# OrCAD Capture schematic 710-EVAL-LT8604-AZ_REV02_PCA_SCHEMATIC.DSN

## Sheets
1 PAGE1
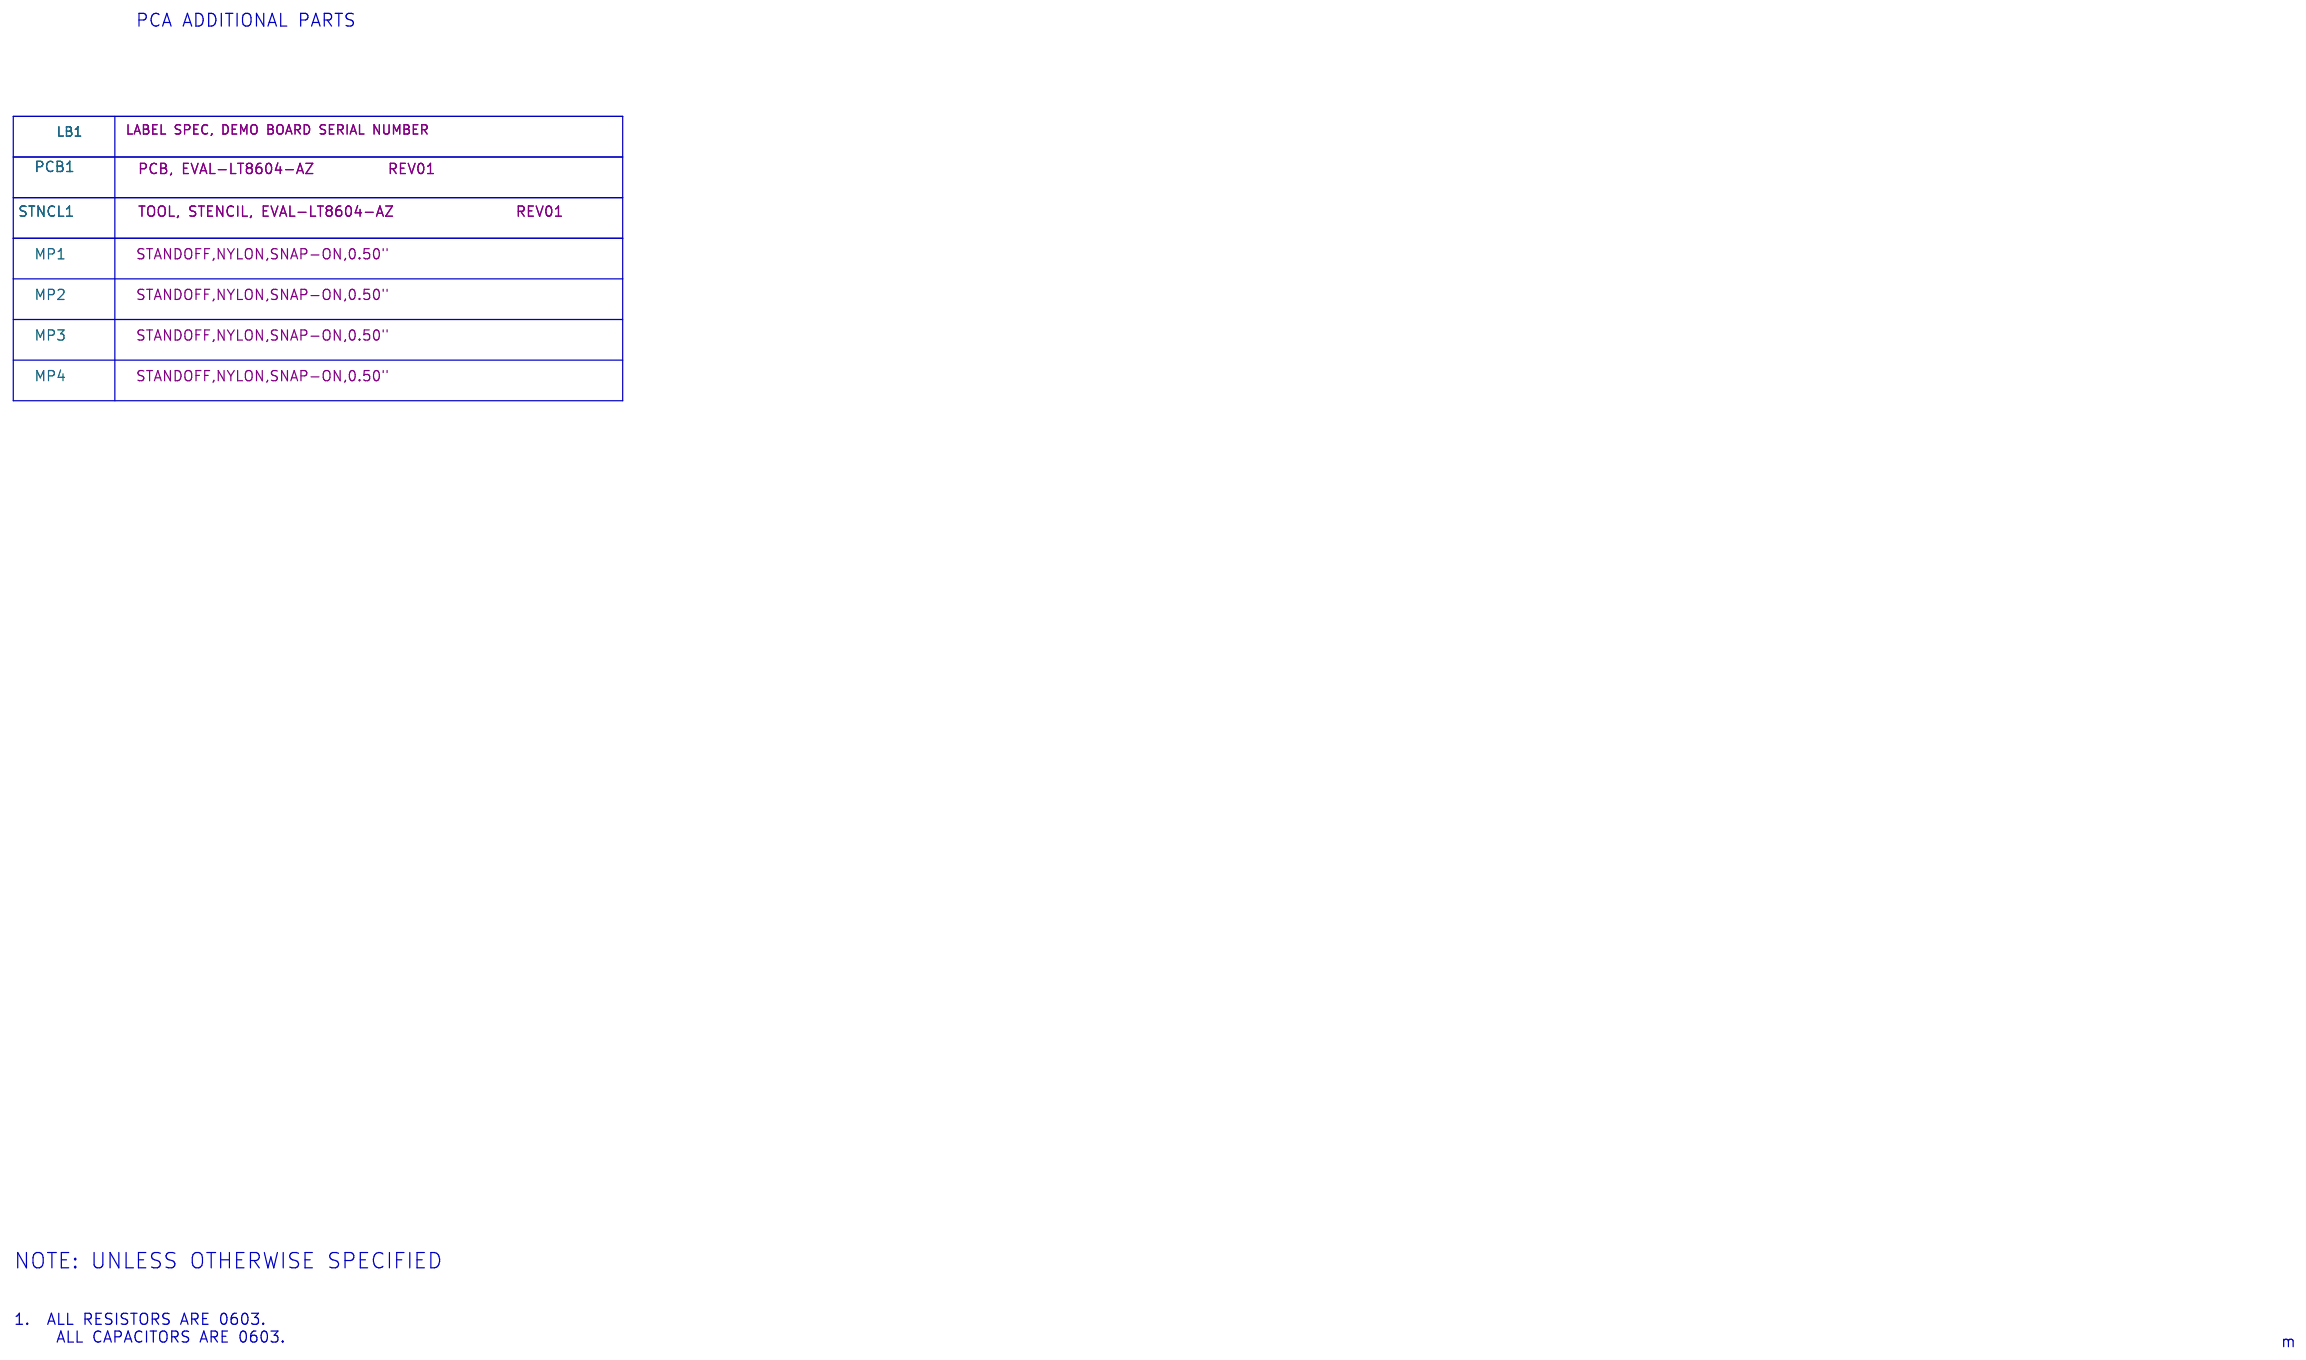
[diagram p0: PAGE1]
2 LT8604: size Custom; company: ANALOG DEVICES; note: DEMO BOARD BILL OF MATERIALS; note: HIGH EFFICIENCY 42V/120mA SYNCHRONOUS BUCK
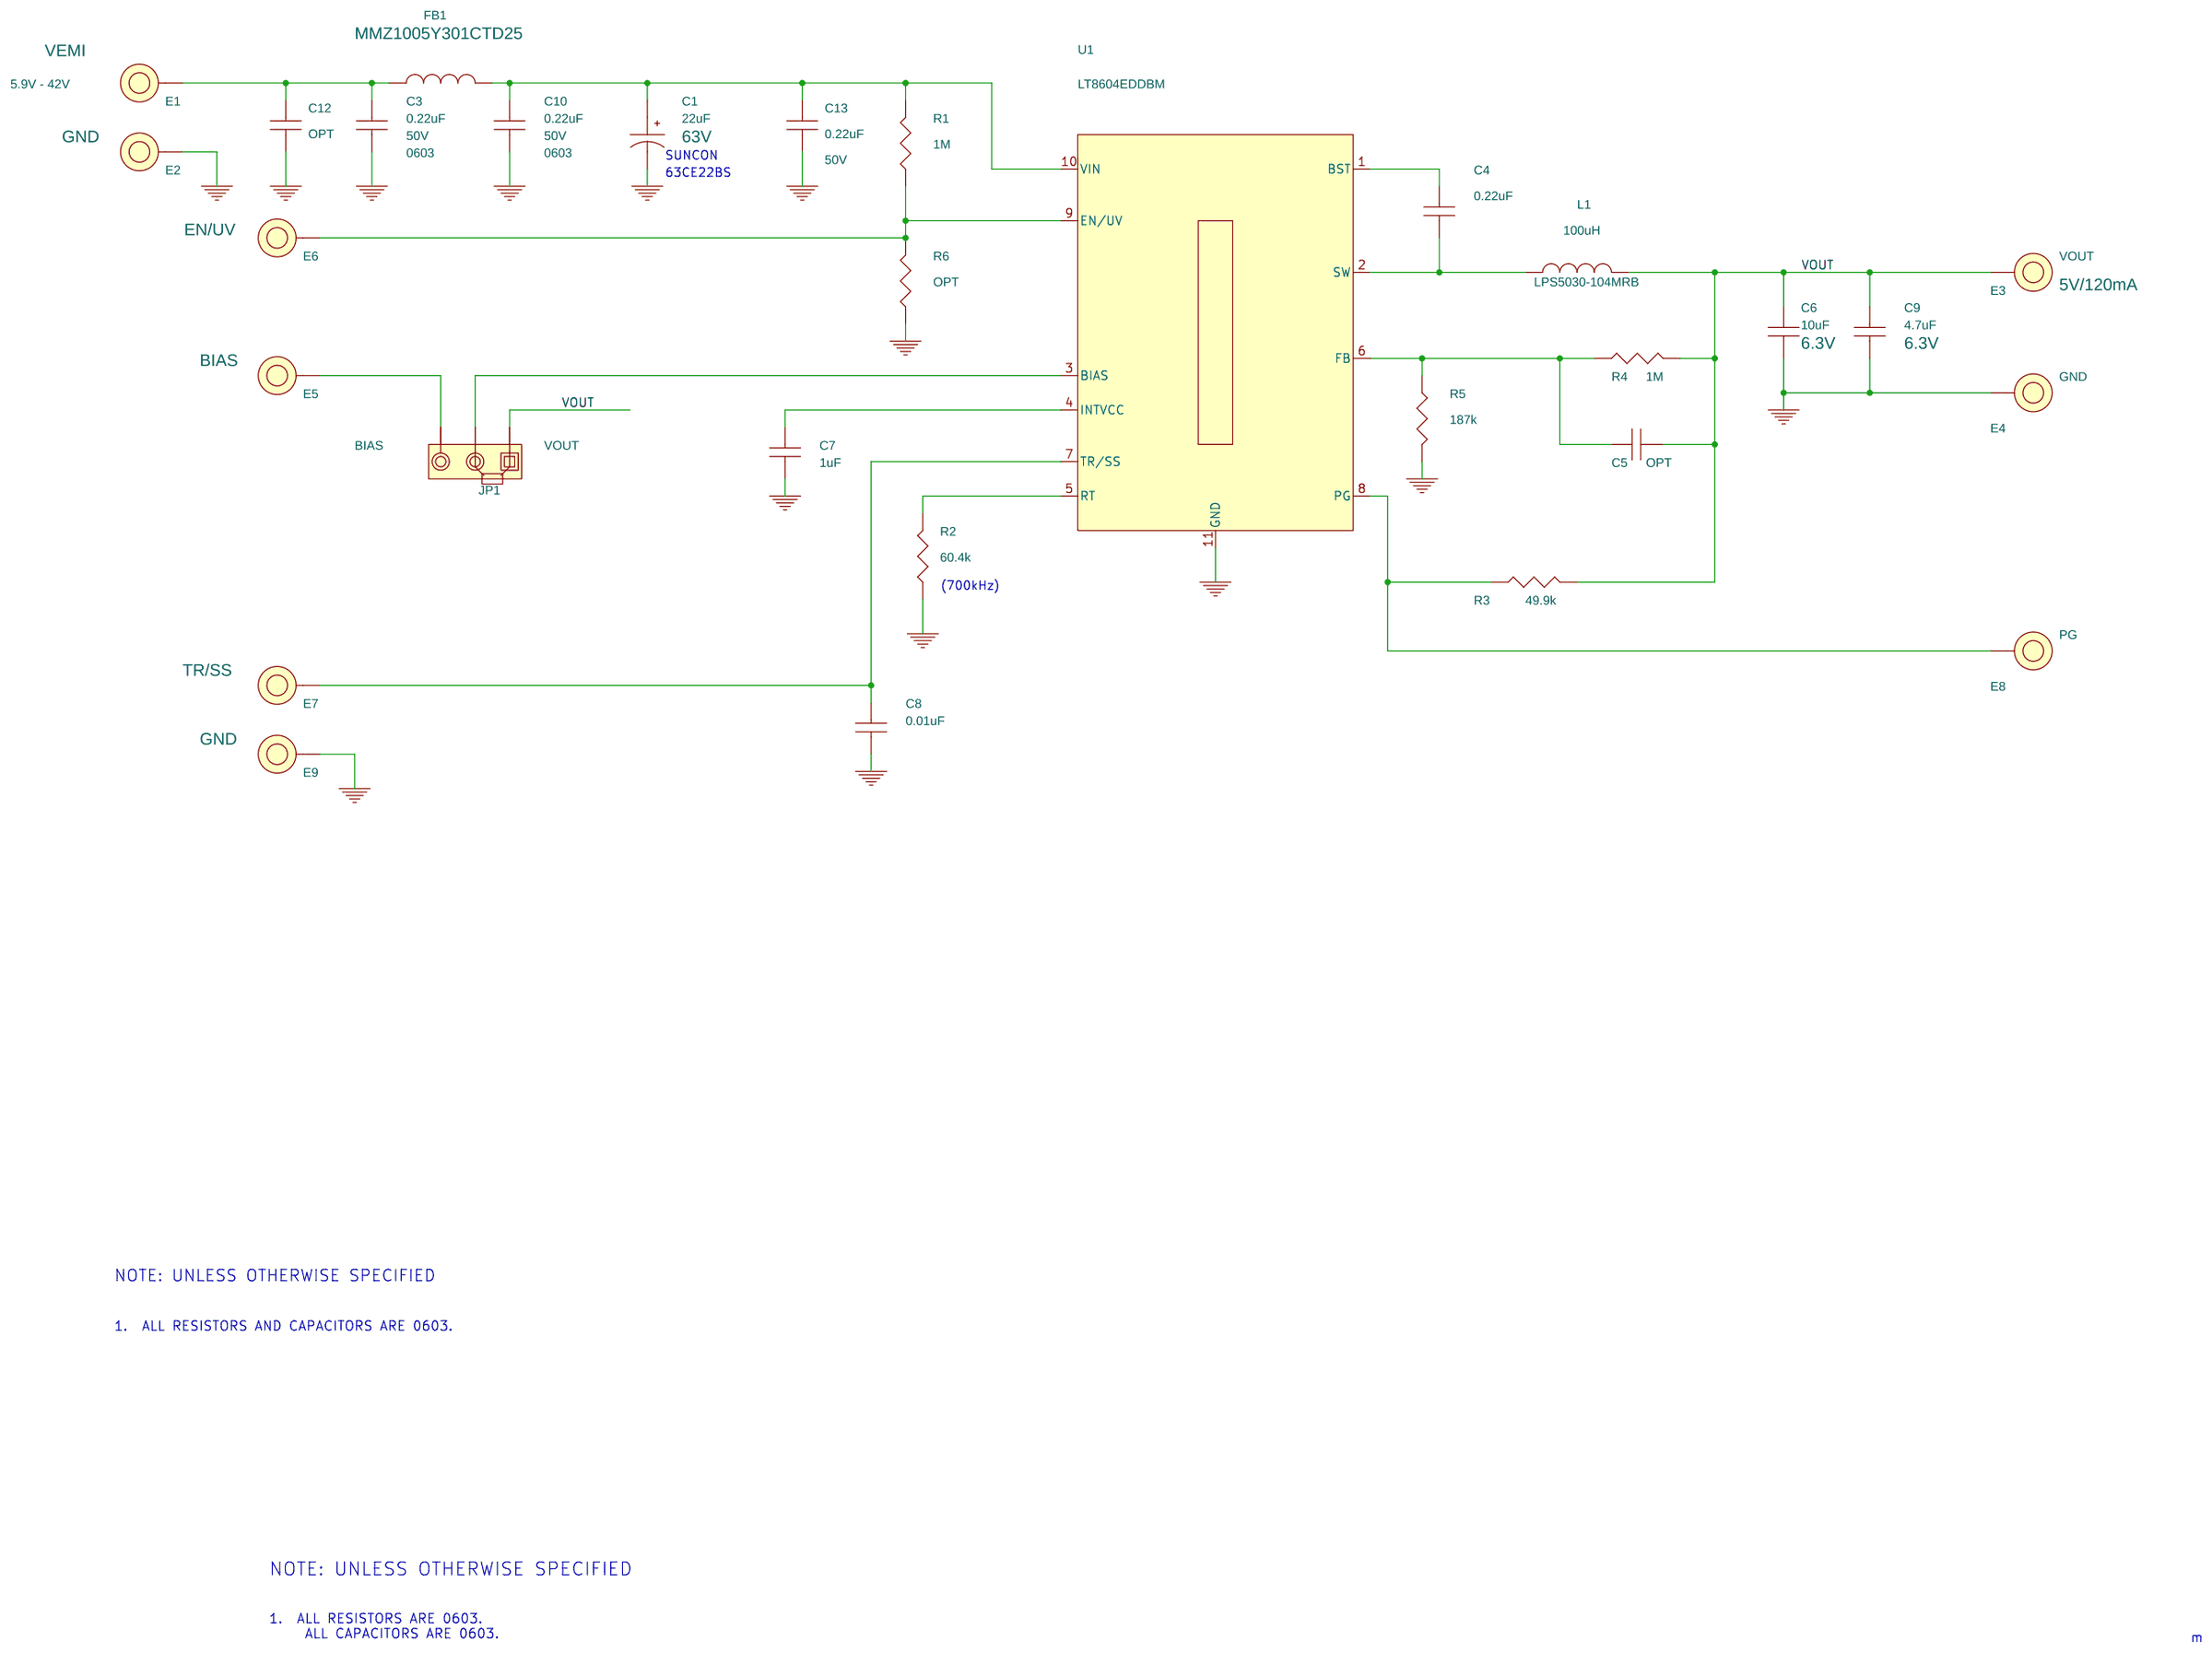
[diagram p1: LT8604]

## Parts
sheet LT8604
C1  22uF  [SUNCON_CE-BS_6.3X7.7]
C3  0.22uF  [CC0603N]
C4  0.22uF  [CC0603N]
C5  OPT  [CC0603N]
C6  10uF  [CC0603N]
C7  1uF  [CC0603N]
C8  0.01uF  [CC0603N]
C9  4.7uF  [CC0603N]
C10  0.22uF  [CC0603N]
C12  OPT  [CC0603N]
C13  0.22uF  [CC0603N]
E1  TEST POINT  [MILLMAX2501]
E2  TEST POINT  [MILLMAX2501]
E3  TEST POINT  [MILLMAX2501]
E4  TEST POINT  [MILLMAX2501]
E5  TEST POINT  [MILLMAX2501]
E6  TEST POINT  [MILLMAX2501]
E7  TEST POINT  [MILLMAX2501]
E8  TEST POINT  [MILLMAX2501]
E9  TEST POINT  [MILLMAX2501]
FB1  300 OHMS@100MHz  [IND0402N]
JP1  HDR  [HD1X3-079]
L1  100uH  [COILCRAFT-LPS5030]
R1  1M  [CR0603N]
R2  60.4k  [CR0603N]
R3  49.9k  [CR0603N]
R4  1M  [CR0603N]
R5  187k  [CR0603N]
R6  OPT  [CR0603N]
U1  LT8604EDDBM  [LTC-DFN-10-1722]
XJP1  SHUNT
sheet PAGE1
LB1  LABEL  [895-0154_REV01]
MP1  STANDOFF  [KEYSTONE_8829-8834]
MP2  STANDOFF  [KEYSTONE_8829-8834]
MP3  STANDOFF  [KEYSTONE_8829-8834]
MP4  STANDOFF  [KEYSTONE_8829-8834]
PCB1  PCB, EVAL-LT8604-AZ
STNCL1  TOOL, STENCIL, EVAL-LT8604-AZ

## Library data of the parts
C1 = CAP_P: CAP.,22uF,ALUM ELECT,63V,20%,6.3x7.7mm,CE-BS Series; CLASS: DISCRETE; Dielectric Type: ALUM ELECT; Inventory Qty: 35661; Manufacturer: SUN ELECTRONIC INDUSTRIES CORP; Manufacturer PN: 63CE22BS; PART_NUMBER: 150-3334; Package Size: 6.3x7.7mm; Rated Voltage: 63V; Tolerance: 20%
C3 C10 C13 = CAP: CAP.,0.22uF,X7R,50V,10%,0603,AEC-Q200; CLASS: DISCRETE; Dielectric Type: X7R; FPLIST: CC0603N,CC0603L,CC0603M; Inventory Qty: 270; Manufacturer: MURATA; Manufacturer PN: GCM188R71H224KA64D; PART_NUMBER: 150-1665; Package Size: 0603; Package Type: Surface Mount, MLCC; Rated Voltage: 50V; Temperature Coefficient: X7R; Tolerance: 10%
C4 = CAP: CAP.,0.22uF,X7R,16V,10%,0603; CLASS: DISCRETE; Dielectric Type: X7R; FPLIST: CC0603N,CC0603L,CC0603M; Inventory Qty: 17079; Manufacturer: AVX; Manufacturer PN: 0603YC224KAT2A; PART_NUMBER: 150-0181; Package Size: 0603; Rated Voltage: 16V; Tolerance: 10%
C5 C12 = CAP: CAP., OPTION, 0603; CLASS: DISCRETE; FPLIST: CC0603N,CC0603L,CC0603M; PART_NUMBER: 150-3038; Package Size: 0603; Package Type: SMD
C6 = CAP: CAP.,10uF,X5R,6.3V,20%,0603; CLASS: DISCRETE; Dielectric Type: X5R; FPLIST: CC0603N,CC0603L,CC0603M; Inventory Qty: 62511; Manufacturer: MURATA; Manufacturer PN: GRM188R60J106ME47D; PART_NUMBER: 150-3401; Package Size: 0603; Package Type: SMD; Rated Voltage: 6.3V; Tolerance: 20%
C7 = CAP: CAP.,1uF,X7R,16V,10%,0603; CLASS: DISCRETE; Dielectric Type: X7R; Inventory Qty: 29099; Manufacturer: KEMET; Manufacturer PN: C0603C105K4RAC7867; PART_NUMBER: 150-0179; Package Size: 0603; Rated Voltage: 16V; Tolerance: 10%
C8 = CAP: CAP.,0.01uF,X7R,16V,10%,0603; CLASS: DISCRETE; Dielectric Type: X7R; FPLIST: CC0603N,CC0603L,CC0603M; Inventory Qty: 67002; Manufacturer: AVX; Manufacturer PN: 0603YC103KAT2A; PART_NUMBER: 150-0038; Package Size: 0603; Rated Voltage: 16V; Tolerance: 10%
C9 = CAP: CAP.,4.7uF,X5R,6.3V,10%,0603; CLASS: DISCRETE; Dielectric Type: X5R; FPLIST: CC0603N,CC0603L,CC0603M; Inventory Qty: 29970; Manufacturer: KEMET; Manufacturer PN: C0603C475K9PACTU; PART_NUMBER: 150-0129; Package Size: 0603; Rated Voltage: 6.3V; Tolerance: 10%
E1 = TESTPOINT_.219_MILL-MAX_2501_A: TEST POINT,TURRET,0.094" MTG. HOLE,PCB 0.062" THK; CLASS: IO; Inventory Qty: 823526; Manufacturer: MILL-MAX; Manufacturer PN: 2501-2-00-80-00-00-07-0; PART_FIELD_01: 5.9V - 42V; PART_FIELD_02: VEMI; PART_NUMBER: 260-0003
E2 E9 = TESTPOINT_.219_MILL-MAX_2501_A: TEST POINT,TURRET,0.094" MTG. HOLE,PCB 0.062" THK; CLASS: IO; Inventory Qty: 823526; Manufacturer: MILL-MAX; Manufacturer PN: 2501-2-00-80-00-00-07-0; PART_FIELD_02: GND; PART_NUMBER: 260-0003
E3 = TESTPOINT_.219_MILL-MAX_2501_A: TEST POINT,TURRET,0.094" MTG. HOLE,PCB 0.062" THK; CLASS: IO; Inventory Qty: 823526; Manufacturer: MILL-MAX; Manufacturer PN: 2501-2-00-80-00-00-07-0; PART_FIELD_01: VOUT; PART_FIELD_02: 5V/120mA; PART_NUMBER: 260-0003
E4 = TESTPOINT_.219_MILL-MAX_2501_A: TEST POINT,TURRET,0.094" MTG. HOLE,PCB 0.062" THK; CLASS: IO; Inventory Qty: 823526; Manufacturer: MILL-MAX; Manufacturer PN: 2501-2-00-80-00-00-07-0; PART_FIELD_01: GND; PART_NUMBER: 260-0003
E5 = TESTPOINT_.219_MILL-MAX_2501_A: TEST POINT,TURRET,0.094" MTG. HOLE,PCB 0.062" THK; CLASS: IO; Inventory Qty: 823526; Manufacturer: MILL-MAX; Manufacturer PN: 2501-2-00-80-00-00-07-0; PART_FIELD_02: BIAS; PART_NUMBER: 260-0003
E6 = TESTPOINT_.219_MILL-MAX_2501_A: TEST POINT,TURRET,0.094" MTG. HOLE,PCB 0.062" THK; CLASS: IO; Inventory Qty: 823526; Manufacturer: MILL-MAX; Manufacturer PN: 2501-2-00-80-00-00-07-0; PART_FIELD_02: EN/UV; PART_NUMBER: 260-0003
E7 = TESTPOINT_.219_MILL-MAX_2501_A: TEST POINT,TURRET,0.094" MTG. HOLE,PCB 0.062" THK; CLASS: IO; Inventory Qty: 823526; Manufacturer: MILL-MAX; Manufacturer PN: 2501-2-00-80-00-00-07-0; PART_FIELD_02: TR/SS; PART_NUMBER: 260-0003
E8 = TESTPOINT_.219_MILL-MAX_2501_A: TEST POINT,TURRET,0.094" MTG. HOLE,PCB 0.062" THK; CLASS: IO; Inventory Qty: 823526; Manufacturer: MILL-MAX; Manufacturer PN: 2501-2-00-80-00-00-07-0; PART_FIELD_01: PG; PART_NUMBER: 260-0003
FB1 = IND: IND.,300 OHMS@100MHz,FERRITE BEAD,25%,250mA,380mOHMS,0402,1LN,AEC-Q200; CLASS: DISCRETE; FPLIST: IND0402N,IND0402L,IND0402M; Inventory Qty: 1000; Manufacturer: TDK; Manufacturer PN: MMZ1005Y301CTD25; PART_NUMBER: 200-0804; Package Size: 0402; Tolerance: 25%
JP1 = 1X3_A: CONN.,HDR,MALE,1x3,2mm,VERT,ST,THT,NO SUBS. ALLOWED; 10th Part Field: BIAS; 9th Part Field: VOUT; CLASS: IO; Inventory Qty: 28997; Manufacturer: Wurth Elektronik; Manufacturer PN: 62000311121; PART_NUMBER: 250-0639
L1 = IND: IND.,100uH,PWR,SHIELDED,20%,0.75A,600mOHMS,4.9x4.9x3,AEC-Q200; CLASS: DISCRETE; Inventory Qty: 0; Manufacturer: COILCRAFT; Manufacturer PN: LPS5030-104MRB; PART_NUMBER: 200-0844; Package Size: 4.9x4.9x3; Tolerance: 20%
R1 R4 = RES: RES.,1M OHM,1%,1/10W,0603,AEC-Q200; CLASS: DISCRETE; FPLIST: CR0603N,CR0603L,CR0603M; Inventory Qty: 165718; Manufacturer: VISHAY; Manufacturer PN: CRCW06031M00FKEA; PART_NUMBER: 100-0335; Package Size: 0603; Rated Power: 1/10W; Temperature Coefficient: 100ppm; Tolerance: 1%
R2 = RES: RES.,60.4k OHMS,1%,1/10W,0603,AEC-Q200; CLASS: DISCRETE; FPLIST: CR0603N,CR0603L,CR0603M; Inventory Qty: 58849; Manufacturer: VISHAY; Manufacturer PN: CRCW060360K4FKEA; PART_NUMBER: 100-2367; Package Size: 0603; Rated Power: 1/10W; Temperature Coefficient: 100ppm/C; Tolerance: 1%
R3 = RES: RES.,49.9k OHMS,1%,1/10W,0603; CLASS: DISCRETE; Inventory Qty: 100527; Manufacturer: NIC; Manufacturer PN: NRC06F4992TRF; PART_NUMBER: 100-0303; Package Size: 0603; Rated Power: 1/10W; Temperature Coefficient: 100ppm/C; Tolerance: 1%
R5 = RES: RES.,187k OHMS,1%,1/10W,0603,AEC-Q200; CLASS: DISCRETE; FPLIST: CR0603N,CR0603L,CR0603M; Inventory Qty: 18483; Manufacturer: PANASONIC; Manufacturer PN: ERJ3EKF1873V; PART_NUMBER: 100-2915; Package Size: 0603; Rated Power: 1/10W; Temperature Coefficient: +/-100; Tolerance: 1%
R6 = RES: RES., OPTION, 0603; CLASS: DISCRETE; FPLIST: CR0603N,CR0603L,CR0603M; PART_NUMBER: 100-2374; Package Size: 0603
U1 = LT8604-DDB: IC,42V 100mA Buck Regulator,DFN-10; CLASS: IC; Inventory Qty: 0; Manufacturer: ANALOG DEVICES; Manufacturer PN: LT8604EDDBM#PBF; PART_NUMBER: LT8604EDDBM#PBF; Package Type: DFN-10
XJP1 = SHUNT_2MM: CONN.,SHUNT,FEMALE,2 POS,2mm; CLASS: IO; Inventory Qty: 64675; Manufacturer: Wurth Elektronik; Manufacturer PN: 60800213421; PART_NUMBER: 250-0485
LB1 = BLANK_LABEL: LABEL SPEC, DEMO BOARD SERIAL NUMBER; Inventory Qty: 0; Manufacturer: BRADY; Manufacturer PN: THT-96-717-10; PART_NUMBER: 895-0154
MP1-MP4 = BLANK_MECHANICAL_PART: STANDOFF,NYLON,SNAP-ON,0.50"; CLASS: DISCRETE; Inventory Qty: 9249; Manufacturer: WURTH ELEKTRONIK; Manufacturer PN: 702935000; PART_NUMBER: 763-0020
PCB1 = BLANK_PCB_PART: BOM Notes: REV01; CLASS: DISCRETE; Inventory Qty: 0; Manufacturer: ADI APPROVED SUPPLIER; Manufacturer PN: 600-EVAL-LT8604-AZ; PART_NUMBER: 600-EVAL-LT8604-AZ
STNCL1 = BLANK_STENCIL_PART: BOM Notes: REV01; CLASS: DISCRETE; Inventory Qty: 0; Manufacturer: ADI APPROVED SUPPLIER; Manufacturer PN: 830-EVAL-LT8604-AZ; PART_NUMBER: 830-EVAL-LT8604-AZ

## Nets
Dgnd: C1.2 C3.2 C6.2 C7.2 C8.2 C9.2 C10.2 C12.2 C13.2 E2.1 E4.1 E9.1 R2.1 R5.2 R6.1 U1.11(GND)
VOUT: C5.2 C6.1 C9.1 E3.1 JP1.1 L1.2 R3.2 R4.2
N16999468: C3.1 C12.1 E1.1 FB1.1
N16999482: C1.1 C10.1 C13.1 FB1.2 R1.2 U1.10(VIN)
N16999621: C4.1 U1.1(BST)
N16999658: E6.1 R1.1 R6.2 U1.9(EN/UV)
N16999666: C4.2 L1.1 U1.2(SW)
N16999756: C5.1 R4.1 R5.1 U1.6(FB)
N16999774: E5.1 JP1.3
N16999778: JP1.2 U1.3(BIAS)
N16999808: C7.1 U1.4(INTVCC)
N16999846: C8.1 E7.1 U1.7(TR/SS)
N16999856: R2.2 U1.5(RT)
N16999860: E8.1 R3.1 U1.8(PG)

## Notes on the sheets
sheet 1
- PCA ADDITIONAL PARTS
- NOTE: UNLESS OTHERWISE SPECIFIED
- 1.  ALL RESISTORS ARE 0603.
       ALL CAPACITORS ARE 0603.
- m
sheet 2
- SUNCON
- 63CE22BS
- (700kHz)
- NOTE: UNLESS OTHERWISE SPECIFIED
- 1.  ALL RESISTORS AND CAPACITORS ARE 0603.
- NOTE: UNLESS OTHERWISE SPECIFIED
- 1.  ALL RESISTORS ARE 0603.
       ALL CAPACITORS ARE 0603.
- m
